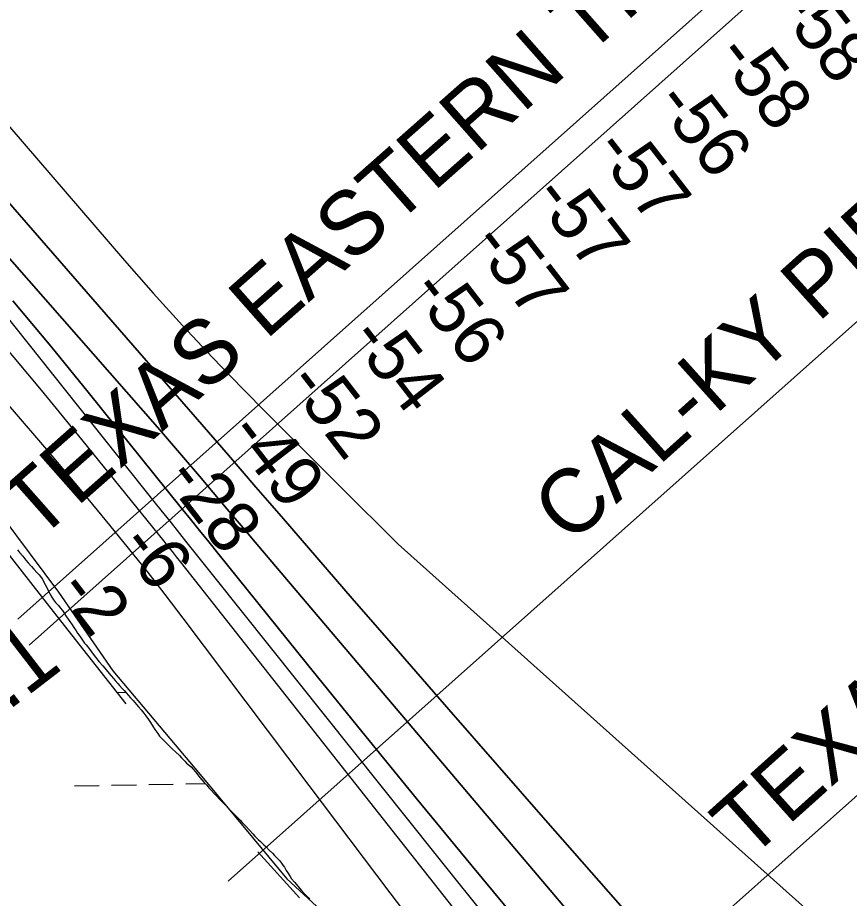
# Model space of a CAD drawing. Extents: x 3903937 to 3942190, y 260677 to 286651.
# Drawn here: x 3925742 to 3926819, y 274427 to 275569 of the extents above; entities that cross this region are included whole.
import ezdxf

# ---------------------------------------------------------------- set-up
doc = ezdxf.new("R2010")
doc.units = 0
for name, color, linetype in [('V-RIVR-EDGE', 7, 'Continuous'), ('V-RIVR-RANG', 7, 'Continuous'), ('V-RIVR-RANG-IDEN', 7, 'Continuous'), ('V-RRAP-FSHR', 7, 'Continuous'), ('V-TOPO-DPTH', 7, 'Continuous'), ('V-TOPO-MAJR', 7, 'Continuous'), ('V-TOPO-MINR', 7, 'Continuous'), ('V-UTIL-IDEN', 7, 'Continuous'), ('V-UTIL-LINE', 7, 'Continuous'), ('V-WETL-SWMP', 7, 'Continuous')]:
    doc.layers.add(name, color=color, linetype=linetype)

msp = doc.modelspace()

# ---------------------------------------------------------------- linework, layer by layer
at = {"layer": 'V-RIVR-EDGE'}
msp.add_lwpolyline([(3925056.9, 275630.2), (3925314.1, 275376.2), (3925378.1, 275316.4), (3925470.4, 275209.4), (3925555.5, 275119.1), (3925641.5, 275028.8), (3925721.3, 274922.8), (3925794.7, 274824.2), (3925865.1, 274722.4), (3925978.4, 274588), (3926090.7, 274452.6), (3926156.8, 274391.8), (3926205.1, 274351.9), (3926231.4, 274303.6), (3926349.9, 274187.1), (3926419.2, 274112.6), (3926441.3, 274069.6), (3926492.7, 274003.4), (3926517.9, 273967.8), (3926556.7, 273913.2), (3926592.4, 273867), (3926597.9, 273845.3)], dxfattribs=at)
at = {"layer": 'V-RRAP-FSHR'}
for points in [[(3925882.3, 274679.5), (3925832.9, 274742.4), (3925783.6, 274805.4), (3925734.2, 274868.3), (3925684.8, 274931.3), (3925635.5, 274994.2), (3925586.1, 275057.2), (3925535.5, 275118.7), (3925482.2, 275178.8), (3925429.3, 275238.8), (3925376.5, 275298.9), (3925320.4, 275355.8), (3925263.4, 275412), (3925206.4, 275468.2), (3925149.5, 275524.3), (3925092.7, 275580.7)], [(3926052.8, 274487.6), (3926107, 274428.2)]]:
    msp.add_lwpolyline(points, dxfattribs=at)
at = {"layer": 'V-TOPO-DPTH'}
for points in [[(3926824.1, 273970.5), (3926811.3, 273986.1), (3926798.4, 274001.7), (3926785.5, 274017.2), (3926685.3, 274137.1), (3926622.1, 274212.5), (3926558.9, 274287.8), (3926495.4, 274362.9), (3926431.9, 274438), (3926049.4, 274889.2), (3926031.4, 274910.5), (3926013.3, 274931.8), (3925995.3, 274953.2), (3925977.3, 274974.5), (3925959.3, 274995.8), (3925941.1, 275017), (3925922.9, 275038.1), (3925904.5, 275059.1), (3925586.2, 275421.6), (3925570.5, 275439.4), (3925554.7, 275457.2), (3925538.8, 275474.9), (3925522.9, 275492.5), (3925400.1, 275628)], [(3926824.1, 273970.5), (3926811.3, 273986.1), (3926798.4, 274001.7), (3926785.5, 274017.2), (3926685.3, 274137.1), (3926622.1, 274212.5), (3926558.9, 274287.8), (3926495.4, 274362.9), (3926431.9, 274438), (3926049.4, 274889.2), (3926031.4, 274910.5), (3926013.3, 274931.8), (3925995.3, 274953.2), (3925977.3, 274974.5), (3925959.3, 274995.8), (3925941.1, 275017), (3925922.9, 275038.1), (3925904.5, 275059.1), (3925586.2, 275421.6), (3925570.5, 275439.4), (3925554.7, 275457.2), (3925538.8, 275474.9), (3925522.9, 275492.5), (3925400.1, 275628)], [(3925637, 275435.8), (3926014.8, 275001.6), (3926032.6, 274981), (3926050.5, 274960.5), (3926068.4, 274939.8), (3926086.2, 274919.2), (3926175.3, 274816.2), (3926237.7, 274744.1), (3926300.3, 274672.2), (3926363, 274600.4), (3926425.8, 274528.6), (3926705, 274210.8), (3926722.7, 274190.7), (3926740.5, 274170.6), (3926758.4, 274150.7), (3926776.3, 274130.8), (3926784.8, 274121.4), (3926798.5, 274106.2), (3926812.2, 274090.9), (3926825.8, 274075.6)], [(3926825.8, 274075.6), (3926812.2, 274090.9), (3926798.5, 274106.2), (3926784.8, 274121.4), (3926776.3, 274130.8), (3926758.4, 274150.7), (3926740.5, 274170.6), (3926722.7, 274190.7), (3926705, 274210.8), (3926425.8, 274528.6), (3926363, 274600.4), (3926300.3, 274672.2), (3926237.7, 274744.1), (3926175.3, 274816.2), (3926086.2, 274919.2), (3926068.4, 274939.8), (3926050.5, 274960.5), (3926032.6, 274981), (3926014.8, 275001.6), (3925637, 275435.8)], [(3926834.3, 273863.5), (3926815.5, 273886.6), (3926790, 273917.9), (3926764.3, 273949.1), (3926738.6, 273980.2), (3926712.8, 274011.2), (3926400.3, 274385.5), (3926329.1, 274471.3), (3926258.1, 274557.4), (3926187.6, 274643.8), (3926117.4, 274730.5), (3926001.1, 274874.8), (3925989.3, 274889.5), (3925977.4, 274904.2), (3925965.6, 274918.9), (3925953.8, 274933.6), (3925833.2, 275083.6), (3925784.6, 275143.1), (3925735.4, 275202)], [(3925735.4, 275202), (3925784.6, 275143.1), (3925833.2, 275083.6), (3925953.8, 274933.6), (3925965.6, 274918.9), (3925977.4, 274904.2), (3925989.3, 274889.5), (3926001.1, 274874.8), (3926117.4, 274730.5), (3926187.6, 274643.8), (3926258.1, 274557.4), (3926329.1, 274471.3), (3926400.3, 274385.5), (3926712.8, 274011.2), (3926738.6, 273980.2), (3926764.3, 273949.1), (3926790, 273917.9), (3926815.5, 273886.6), (3926834.3, 273863.5)], [(3925719.2, 275149.5), (3925772.3, 275085.9), (3925824.7, 275021.9), (3925931, 274890.3), (3925936.4, 274883.6), (3925941.8, 274876.8), (3925947.2, 274870), (3925952.6, 274863.2), (3926597, 274045.7), (3926615.5, 274022.2), (3926634, 273998.7), (3926652.6, 273975.2), (3926671.1, 273951.8), (3926702.6, 273911.9), (3926705.4, 273908.4), (3926708.2, 273904.8), (3926711, 273901.3), (3926713.8, 273897.7), (3926956.1, 273589.6)]]:
    msp.add_lwpolyline(points, dxfattribs=at)
at = {"layer": 'V-TOPO-MAJR'}
msp.add_lwpolyline([(3925589.3, 275587), (3925610.7, 275564.3), (3925631.8, 275541.4), (3925652.5, 275518.2), (3925673, 275494.7), (3925880.2, 275253.9), (3925917.4, 275211.6), (3925955.2, 275169.8), (3925993.9, 275128.8), (3926033.1, 275088.3), (3926065.1, 275056), (3926088.9, 275032.1), (3926112.6, 275008.3), (3926136.4, 274984.5), (3926160.3, 274960.8), (3926235, 274886.6), (3926933.5, 274261.2)], dxfattribs=at)
at = {"layer": 'V-TOPO-MINR'}
for points in [[(3925400.1, 275628), (3925522.9, 275492.5), (3925538.8, 275474.9), (3925554.7, 275457.2), (3925570.5, 275439.4), (3925586.2, 275421.6), (3925904.5, 275059.1), (3925922.9, 275038.1), (3925941.1, 275017), (3925959.3, 274995.8), (3925977.3, 274974.5), (3925995.3, 274953.2), (3926013.3, 274931.8), (3926031.4, 274910.5), (3926049.4, 274889.2), (3926431.9, 274438), (3926495.4, 274362.9), (3926558.9, 274287.8), (3926622.1, 274212.5), (3926685.3, 274137.1), (3926785.5, 274017.2), (3926798.4, 274001.7), (3926811.3, 273986.1), (3926824.1, 273970.5)], [(3925637, 275435.8), (3926014.8, 275001.6), (3926032.6, 274981), (3926050.5, 274960.5), (3926068.4, 274939.8), (3926086.2, 274919.2), (3926175.3, 274816.2), (3926237.7, 274744.1), (3926300.3, 274672.2), (3926363, 274600.4), (3926425.8, 274528.6), (3926705, 274210.8), (3926722.7, 274190.7), (3926740.5, 274170.6), (3926758.4, 274150.7), (3926776.3, 274130.8), (3926784.8, 274121.4), (3926798.5, 274106.2), (3926812.2, 274090.9), (3926825.8, 274075.6)], [(3925393.9, 275427.9), (3925454.7, 275367.3), (3925459.3, 275362.6), (3925463.8, 275358), (3925468.3, 275353.3), (3925472.7, 275348.5), (3925643.7, 275162.6), (3925689.4, 275112), (3925734.6, 275061), (3925779, 275009.3), (3925822.8, 274957.1), (3925860.8, 274911.2), (3925885, 274881.4), (3925909, 274851.5), (3925932.5, 274821.2), (3925955.8, 274790.7), (3926119.1, 274573.7), (3926224.1, 274434.6), (3926329.3, 274295.9), (3926435, 274157.4), (3926541, 274019.2), (3927114, 273274.5)], [(3925619.6, 275316.4), (3925921.6, 274937.6), (3925940.5, 274914), (3925959.3, 274890.3), (3925978.2, 274866.6), (3925997.1, 274842.9), (3926282.2, 274485.7), (3926357.1, 274392), (3926432.2, 274298.4), (3926507.5, 274205), (3926582.9, 274111.6), (3926707.6, 273957.5), (3926720.8, 273941.3), (3926733.9, 273925.1), (3926746.9, 273908.8), (3926760, 273892.5), (3927064.3, 273511.1)], [(3925735.4, 275202), (3925784.6, 275143.1), (3925833.2, 275083.6), (3925953.8, 274933.6), (3925965.6, 274918.9), (3925977.4, 274904.2), (3925989.3, 274889.5), (3926001.1, 274874.8), (3926117.4, 274730.5), (3926187.6, 274643.8), (3926258.1, 274557.4), (3926329.1, 274471.3), (3926400.3, 274385.5), (3926712.8, 274011.2), (3926738.6, 273980.2), (3926764.3, 273949.1), (3926790, 273917.9), (3926815.5, 273886.6), (3926834.3, 273863.5)], [(3925719.2, 275149.5), (3925772.3, 275085.9), (3925824.7, 275021.9), (3925931, 274890.3), (3925936.4, 274883.6), (3925941.8, 274876.8), (3925947.2, 274870), (3925952.6, 274863.2), (3926597, 274045.7), (3926615.5, 274022.2), (3926634, 273998.7), (3926652.6, 273975.2), (3926671.1, 273951.8), (3926702.6, 273911.9), (3926705.4, 273908.4), (3926708.2, 273904.8), (3926711, 273901.3), (3926713.8, 273897.7), (3926956.1, 273589.6)]]:
    msp.add_lwpolyline(points, dxfattribs=at)
at = {"layer": 'V-UTIL-LINE'}
for p, q in [((3928109.5, 276898.2), (3925742.1, 274789.1)), ((3928123.9, 276864.7), (3925756.5, 274755.6)), ((3928382.1, 276558.7), (3926014.7, 274449.5)), ((3928669.1, 276200), (3926301.7, 274090.8))]:
    msp.add_line(p, q, dxfattribs=at)
at = {"layer": 'V-WETL-SWMP'}
for p, q in [((3925741.4, 274879.3), (3925744.2, 274875.8)), ((3925744.2, 274875.8), (3925748.3, 274870.7)), ((3925748.3, 274870.7), (3925752.5, 274865.6)), ((3925752.5, 274865.6), (3925755.3, 274862.3)), ((3925755.3, 274862.3), (3925759.7, 274857.3)), ((3925759.7, 274857.3), (3925762.8, 274854.1)), ((3925762.8, 274854.1), (3925767, 274849.5)), ((3925767, 274849.5), (3925769.5, 274846.7)), ((3925769.5, 274846.7), (3925774.2, 274841.2)), ((3925774.2, 274841.2), (3925775.9, 274837.1)), ((3925775.9, 274837.1), (3925779.2, 274831)), ((3925779.2, 274831), (3925781.1, 274827.2)), ((3925781.1, 274827.2), (3925783.9, 274821.5)), ((3925783.9, 274821.5), (3925786, 274817.6)), ((3925786, 274817.6), (3925788.3, 274814.3)), ((3925788.3, 274814.3), (3925791, 274811)), ((3925791, 274811), (3925794.7, 274806.8)), ((3925794.7, 274806.8), (3925796.7, 274804)), ((3925796.7, 274804), (3925799.7, 274800.4)), ((3925799.7, 274800.4), (3925802.6, 274796.4)), ((3925802.6, 274796.4), (3925804.4, 274793.6)), ((3925804.4, 274793.6), (3925807.4, 274789.2)), ((3925807.4, 274789.2), (3925809.3, 274786.2)), ((3925809.3, 274786.2), (3925812.3, 274781.7)), ((3925812.3, 274781.7), (3925814.5, 274778.5)), ((3925814.5, 274778.5), (3925817.5, 274774.1)), ((3925817.5, 274774.1), (3925819.5, 274771.1)), ((3925819.5, 274771.1), (3925822.3, 274767.1)), ((3925822.3, 274767.1), (3925824.1, 274764.5)), ((3925824.1, 274764.5), (3925825.9, 274761.9)), ((3925825.9, 274761.9), (3925828.6, 274758.3)), ((3925828.6, 274758.3), (3925830.6, 274755.8)), ((3925830.6, 274755.8), (3925835.3, 274749.8)), ((3925835.3, 274749.8), (3925839.7, 274743.8)), ((3925839.7, 274743.8), (3925842.7, 274740)), ((3925842.7, 274740), (3925847.4, 274734)), ((3925847.4, 274734), (3925852, 274728.7)), ((3925852, 274728.7), (3925854.7, 274725.6)), ((3925854.7, 274725.6), (3925858.3, 274721.3)), ((3925858.3, 274721.3), (3925862.9, 274715.8)), ((3925862.9, 274715.8), (3925866, 274712.3)), ((3925866, 274712.3), (3925868.2, 274709.8)), ((3925868.2, 274709.8), (3925871.5, 274706)), ((3925871.5, 274706), (3925873.9, 274703.3)), ((3925873.9, 274703.3), (3925877.3, 274699.5)), ((3925877.3, 274699.5), (3925879.7, 274696.9)), ((3925870.3, 274694.3), (3925881.9, 274694.5)), ((3925879.7, 274696.9), (3925883, 274693.3)), ((3925883, 274693.3), (3925885, 274690.9)), ((3925885, 274690.9), (3925888.1, 274687.4)), ((3925888.1, 274687.4), (3925891.3, 274683.8)), ((3925891.3, 274683.8), (3925893.5, 274681.1)), ((3925893.5, 274681.1), (3925895.7, 274678.5)), ((3925895.7, 274678.5), (3925898.2, 274675.8)), ((3925898.2, 274675.8), (3925901.9, 274671.6)), ((3925901.9, 274671.6), (3925905.4, 274667.2)), ((3925905.4, 274667.2), (3925907.9, 274664)), ((3925907.9, 274664), (3925911.4, 274659)), ((3925911.4, 274659), (3925913.8, 274655.2)), ((3925913.8, 274655.2), (3925917.4, 274649.8)), ((3925917.4, 274649.8), (3925919.6, 274646.1)), ((3925919.6, 274646.1), (3925923.3, 274641.1)), ((3925923.3, 274641.1), (3925925.8, 274637.8)), ((3925925.8, 274637.8), (3925930, 274633.1)), ((3925930, 274633.1), (3925933.3, 274629.7)), ((3925933.3, 274629.7), (3925938.8, 274624.3)), ((3925938.8, 274624.3), (3925942.5, 274620.7)), ((3925942.5, 274620.7), (3925946.3, 274617.4)), ((3925946.3, 274617.4), (3925951.4, 274612.5)), ((3925951.4, 274612.5), (3925954.1, 274609.4)), ((3925954.1, 274609.4), (3925958.2, 274605.2)), ((3925958.2, 274605.2), (3925960.7, 274602.8)), ((3925960.7, 274602.8), (3925966.7, 274597.9)), ((3925966.7, 274597.9), (3925969.4, 274594.7)), ((3925969.4, 274594.7), (3925972.2, 274591.2)), ((3925972.2, 274591.2), (3925977.8, 274583.9)), ((3925815.6, 274573.3), (3925847.6, 274573.8)), ((3925863.6, 274574.1), (3925895.6, 274574.7)), ((3925911.6, 274574.9), (3925943.5, 274575.5)), ((3925959.5, 274575.8), (3925984.6, 274576.2)), ((3925977.8, 274583.9), (3925983.4, 274577.5)), ((3925983.4, 274577.5), (3925986.8, 274574.1)), ((3925986.8, 274574.1), (3925989.7, 274570.7)), ((3925989.7, 274570.7), (3925992.5, 274567.4)), ((3925992.5, 274567.4), (3925996.4, 274563.2)), ((3925996.4, 274563.2), (3925999.3, 274560.3)), ((3925999.3, 274560.3), (3926003.5, 274556)), ((3926003.5, 274556), (3926008, 274551.4)), ((3926008, 274551.4), (3926011.1, 274548.2)), ((3926011.1, 274548.2), (3926015.5, 274543.6)), ((3926015.5, 274543.6), (3926018.5, 274540.6)), ((3926018.5, 274540.6), (3926022.9, 274536.1)), ((3926022.9, 274536.1), (3926025.7, 274533)), ((3926025.7, 274533), (3926030, 274528.6)), ((3926030, 274528.6), (3926032.8, 274525.6)), ((3926032.8, 274525.6), (3926037, 274521.2)), ((3926037, 274521.2), (3926042.5, 274515.4)), ((3926042.5, 274515.4), (3926046.6, 274511)), ((3926046.6, 274511), (3926049.3, 274508.1)), ((3926049.3, 274508.1), (3926053.6, 274503.8)), ((3926053.6, 274503.8), (3926056.5, 274501.1)), ((3926056.5, 274501.1), (3926060.7, 274496.9)), ((3926060.7, 274496.9), (3926063.6, 274494.3)), ((3926063.6, 274494.3), (3926067.8, 274490)), ((3926067.8, 274490), (3926072, 274485.8)), ((3926072, 274485.8), (3926074.8, 274482.9)), ((3926074.8, 274482.9), (3926078.6, 274479.1)), ((3926078.6, 274479.1), (3926080.9, 274476.5)), ((3926080.9, 274476.5), (3926083.8, 274473)), ((3926083.8, 274473), (3926085.6, 274470.4)), ((3926085.6, 274470.4), (3926087.4, 274467.7)), ((3926087.4, 274467.7), (3926089.8, 274463.3)), ((3926089.8, 274463.3), (3926091.8, 274460.3)), ((3926091.8, 274460.3), (3926094.7, 274455.8)), ((3926094.7, 274455.8), (3926096.8, 274452.6)), ((3926096.8, 274452.6), (3926100.3, 274448.2)), ((3926100.3, 274448.2), (3926102.9, 274445.2)), ((3926102.9, 274445.2), (3926106.8, 274440.6)), ((3926106.8, 274440.6), (3926109.6, 274437.5)), ((3926109.6, 274437.5), (3926113.6, 274433.3)), ((3926113.6, 274433.3), (3926116, 274430.5)), ((3926116, 274430.5), (3926120.2, 274426.6))]:
    msp.add_line(p, q, dxfattribs=at)

# ---------------------------------------------------------------- texts
at = {"layer": 'V-RIVR-RANG'}
for s, rotation, p in [('-58', 307.7327, (3926723.7, 275580.8)), ('-58', 307.7327, (3926644.4, 275519.8)), ('-56', 307.7327, (3926565.5, 275458.4)), ('-57', 307.7327, (3926486.1, 275397.6)), ('-57', 307.7327, (3926406.9, 275336.6)), ('-57', 307.7327, (3926327.6, 275275.6)), ('-56', 307.7327, (3926248.6, 275214.4)), ('-54', 307.7327, (3926169.5, 275153.1)), ('-52', 307.7327, (3926088.5, 275094.4)), ('-49', 307.7327, (3926012.3, 275029.5)), ('-28', 307.7327, (3925930.6, 274971.6)), ('-6', 307.7327, (3925871.4, 274884.7)), ('-2', 307.4483, (3925790.7, 274826.1))]:
    msp.add_text(s, height=67, rotation=rotation, dxfattribs=at).set_placement(p)
at = {"layer": 'V-RIVR-RANG-IDEN'}
msp.add_text('R-7.1', height=83, rotation=37.5912, dxfattribs=at).set_placement((3925586.7, 274560.1))
at = {"layer": 'V-UTIL-IDEN'}
for s, rotation, p in [('TEXAS EASTERN TRANSMISSION CO.', 41.4543, (3925767.2, 274888.8)), ('CAL-KY PIPELINE CO.', 41.9212, (3926457.4, 274884.2)), ('TEXACO PIPELINE CO.', 41.8917, (3926689.1, 274475.6))]:
    msp.add_text(s, height=83, rotation=rotation, dxfattribs=at).set_placement(p)

doc.saveas('drawing.dxf')
